Omron CX-Programmer project NuevoProyecto (CX-Programmer 9.50)

# PLC NewPLC1: CP1L-E EM

## Program Lámparas (cyclic task 0)
Local symbols
Etapa_0 10.00 BOOL
Etapa_1 10.01 BOOL
Etapa_10 10.10 BOOL
Etapa_11 10.11 BOOL
Etapa_12 10.12 BOOL
Etapa_13 10.13 BOOL
Etapa_2 10.02 BOOL
Etapa_3 10.03 BOOL
Etapa_8 10.08 BOOL
Etapa_9 10.09 BOOL
H_1 100.00 BOOL
H_2 100.01 BOOL
H_3 100.02 BOOL
T_0 15.00 BOOL
m 0.00 BOOL

### Section Sección1_Programa_principal
; Programa principal (Etapas 0 ... 3)

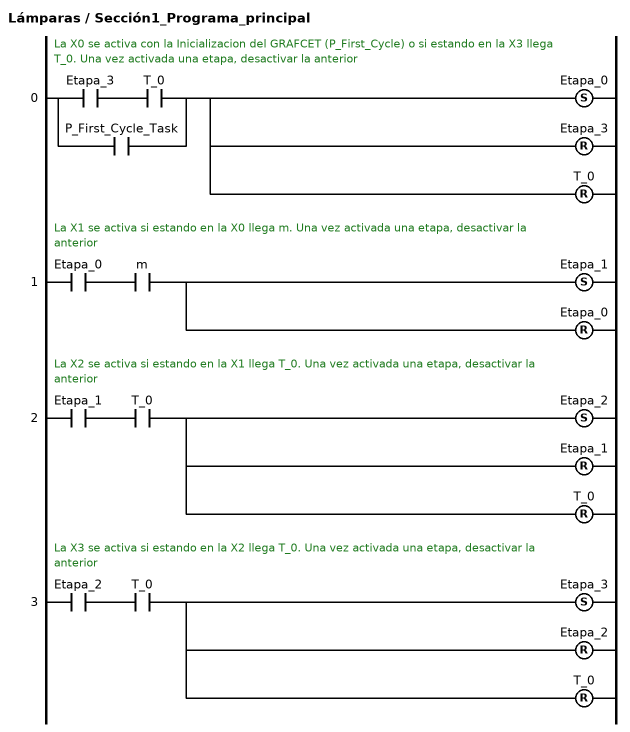
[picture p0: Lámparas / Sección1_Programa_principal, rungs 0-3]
; rung 0: La X0 se activa con la Inicializacion del GRAFCET (P_First_Cycle) o si estando en la X3 llega T_0. Una vez activada una etapa, desactivar la anterior
LD Etapa_3
AND T_0
OR P_First_Cycle_Task
SET Etapa_0
RSET Etapa_3
RSET T_0  // Una vez cumplido su cometido desactivar (reset) inmediatamente la variable auxiliar T_0
; rung 1: La X1 se activa si estando en la X0 llega m. Una vez activada una etapa, desactivar la anterior
LD Etapa_0
AND m
SET Etapa_1
RSET Etapa_0
; rung 2: La X2 se activa si estando en la X1 llega T_0. Una vez activada una etapa, desactivar la anterior
LD Etapa_1
AND T_0
SET Etapa_2
RSET Etapa_1
RSET T_0  // Una vez cumplido su cometido desactivar (reset) inmediatamente la variable auxiliar T_0
; rung 3: La X3 se activa si estando en la X2 llega T_0. Una vez activada una etapa, desactivar la anterior
LD Etapa_2
AND T_0
SET Etapa_3
RSET Etapa_2
RSET T_0  // Una vez cumplido su cometido desactivar (reset) inmediatamente la variable auxiliar T_0

### Section Sección2_Temporizador_T0

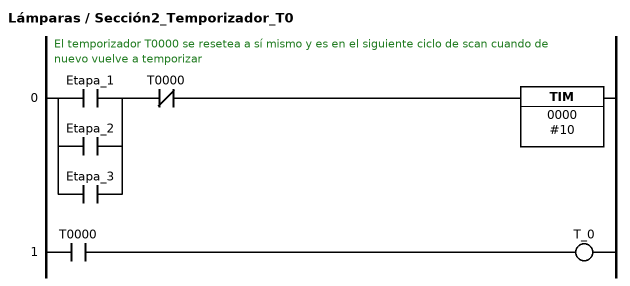
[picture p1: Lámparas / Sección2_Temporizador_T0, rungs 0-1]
; rung 0: El temporizador T0000 se resetea a sí mismo y es en el siguiente ciclo de scan cuando de nuevo vuelve a temporizar
LD Etapa_1
OR Etapa_2
OR Etapa_3
ANDNOT T0000
TIM 0000 #10
; rung 1
LD T0000
OUT T_0

### Section Sección3_Salidas

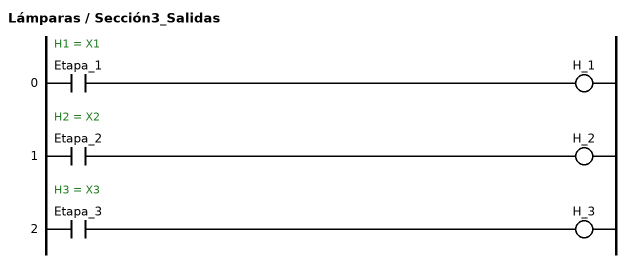
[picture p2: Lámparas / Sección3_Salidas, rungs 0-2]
; rung 0: H1 = X1
LD Etapa_1
OUT H_1
; rung 1: H2 = X2
LD Etapa_2
OUT H_2
; rung 2: H3 = X3
LD Etapa_3
OUT H_3

### Section Sección4_END
; rung 0: Fin de programa
END(001)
